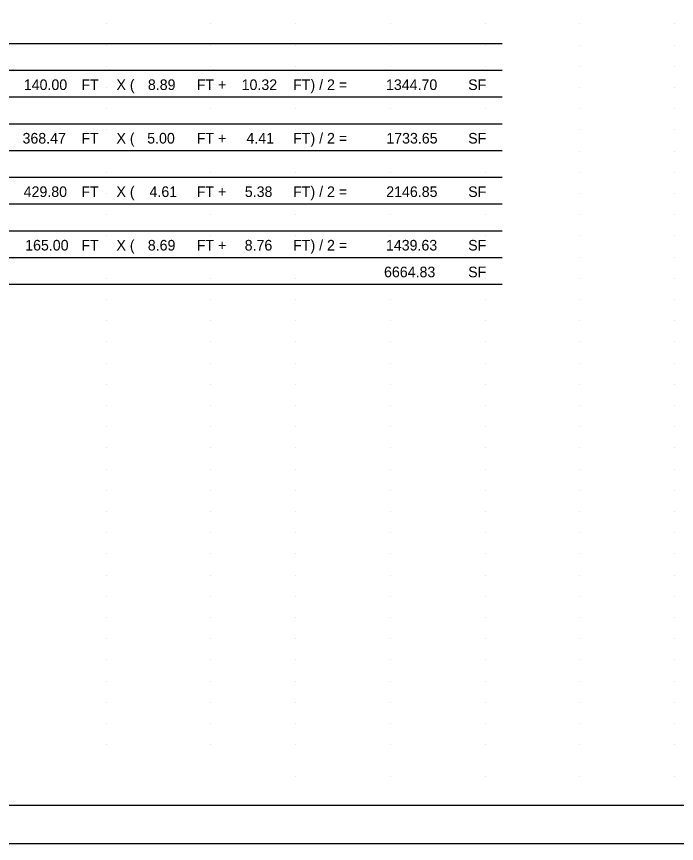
# Model space of a CAD drawing. Extents: x 2073163.5 to 2073197.5, y 634076.4 to 634098.4.
# Drawn here: x 2073171.63 to 2073180.34, y 634076.43 to 634087.36 of the extents above; entities that cross this region are included whole.
import ezdxf

# ---------------------------------------------------------------- set-up
doc = ezdxf.new("R2010")
doc.units = 0
for name, color, linetype in [('SC_Scratch1', 7, 'Continuous'), ('SH_Border', 7, 'Continuous'), ('SH_Cut_Line', 7, 'Continuous'), ('SH_Data', 7, 'Continuous'), ('SH_Text', 7, 'Continuous')]:
    doc.layers.add(name, color=color, linetype=linetype)

msp = doc.modelspace()

# ---------------------------------------------------------------- linework, layer by layer
at = {"layer": 'SC_Scratch1'}
for p, q in [((2073165.829, 634087.001), (2073178.043, 634087.001)), ((2073165.829, 634086.648), (2073178.043, 634086.648)), ((2073165.829, 634086.294), (2073178.043, 634086.294)), ((2073165.829, 634085.941), (2073178.043, 634085.941)), ((2073165.829, 634085.588), (2073178.043, 634085.588)), ((2073165.829, 634085.234), (2073178.043, 634085.234)), ((2073165.829, 634084.881), (2073178.043, 634084.881)), ((2073165.829, 634084.528), (2073178.043, 634084.528)), ((2073165.829, 634084.174), (2073178.043, 634084.174)), ((2073165.829, 634083.821), (2073178.043, 634083.821))]:
    msp.add_line(p, q, dxfattribs=at)
at = {"layer": 'SH_Border'}
msp.add_lwpolyline([(2073165.007, 634097.934), (2073197.007, 634097.934), (2073197.007, 634076.934), (2073165.007, 634076.934)], close=True, dxfattribs=at)
at = {"layer": 'SH_Cut_Line'}
msp.add_lwpolyline([(2073163.507, 634076.434), (2073197.507, 634076.434), (2073197.507, 634098.434), (2073163.507, 634098.434)], close=True, dxfattribs=at)
at = {"layer": 'SH_Data'}
for p, q in [((2073172.821, 634087.258), (2073172.821, 634087.258)), ((2073174.196, 634087.258), (2073174.196, 634087.258)), ((2073175.321, 634087.258), (2073175.321, 634087.258)), ((2073176.571, 634087.258), (2073176.571, 634087.258)), ((2073177.821, 634087.258), (2073177.821, 634087.258)), ((2073179.071, 634087.258), (2073179.071, 634087.258)), ((2073180.321, 634087.258), (2073180.321, 634087.258)), ((2073172.821, 634086.978), (2073172.821, 634086.978)), ((2073174.196, 634086.978), (2073174.196, 634086.978)), ((2073175.321, 634086.978), (2073175.321, 634086.978)), ((2073176.571, 634086.978), (2073176.571, 634086.978)), ((2073177.821, 634086.978), (2073177.821, 634086.978)), ((2073179.071, 634086.978), (2073179.071, 634086.978)), ((2073180.321, 634086.978), (2073180.321, 634086.978)), ((2073172.821, 634086.698), (2073172.821, 634086.698)), ((2073174.196, 634086.698), (2073174.196, 634086.698)), ((2073175.321, 634086.698), (2073175.321, 634086.698)), ((2073176.571, 634086.698), (2073176.571, 634086.698)), ((2073177.821, 634086.698), (2073177.821, 634086.698)), ((2073179.071, 634086.698), (2073179.071, 634086.698)), ((2073180.321, 634086.698), (2073180.321, 634086.698)), ((2073172.821, 634086.418), (2073172.821, 634086.418)), ((2073174.196, 634086.418), (2073174.196, 634086.418)), ((2073175.321, 634086.418), (2073175.321, 634086.418)), ((2073176.571, 634086.418), (2073176.571, 634086.418)), ((2073177.821, 634086.418), (2073177.821, 634086.418)), ((2073179.071, 634086.418), (2073179.071, 634086.418)), ((2073180.321, 634086.418), (2073180.321, 634086.418)), ((2073172.821, 634086.138), (2073172.821, 634086.138)), ((2073174.196, 634086.138), (2073174.196, 634086.138)), ((2073175.321, 634086.138), (2073175.321, 634086.138)), ((2073176.571, 634086.138), (2073176.571, 634086.138)), ((2073177.821, 634086.138), (2073177.821, 634086.138)), ((2073179.071, 634086.138), (2073179.071, 634086.138)), ((2073180.321, 634086.138), (2073180.321, 634086.138)), ((2073172.821, 634085.858), (2073172.821, 634085.858)), ((2073174.196, 634085.858), (2073174.196, 634085.858)), ((2073175.321, 634085.858), (2073175.321, 634085.858)), ((2073176.571, 634085.858), (2073176.571, 634085.858)), ((2073177.821, 634085.858), (2073177.821, 634085.858)), ((2073179.071, 634085.858), (2073179.071, 634085.858)), ((2073180.321, 634085.858), (2073180.321, 634085.858)), ((2073172.821, 634085.578), (2073172.821, 634085.578)), ((2073174.196, 634085.578), (2073174.196, 634085.578)), ((2073175.321, 634085.578), (2073175.321, 634085.578)), ((2073176.571, 634085.578), (2073176.571, 634085.578)), ((2073177.821, 634085.578), (2073177.821, 634085.578)), ((2073179.071, 634085.578), (2073179.071, 634085.578)), ((2073180.321, 634085.578), (2073180.321, 634085.578)), ((2073172.821, 634085.298), (2073172.821, 634085.298)), ((2073174.196, 634085.298), (2073174.196, 634085.298)), ((2073175.321, 634085.298), (2073175.321, 634085.298)), ((2073176.571, 634085.298), (2073176.571, 634085.298)), ((2073177.821, 634085.298), (2073177.821, 634085.298)), ((2073179.071, 634085.298), (2073179.071, 634085.298)), ((2073180.321, 634085.298), (2073180.321, 634085.298)), ((2073172.821, 634085.018), (2073172.821, 634085.018)), ((2073174.196, 634085.018), (2073174.196, 634085.018)), ((2073175.321, 634085.018), (2073175.321, 634085.018)), ((2073176.571, 634085.018), (2073176.571, 634085.018)), ((2073177.821, 634085.018), (2073177.821, 634085.018)), ((2073179.071, 634085.018), (2073179.071, 634085.018)), ((2073180.321, 634085.018), (2073180.321, 634085.018)), ((2073172.821, 634084.738), (2073172.821, 634084.738)), ((2073174.196, 634084.738), (2073174.196, 634084.738)), ((2073175.321, 634084.738), (2073175.321, 634084.738)), ((2073176.571, 634084.738), (2073176.571, 634084.738)), ((2073177.821, 634084.738), (2073177.821, 634084.738)), ((2073179.071, 634084.738), (2073179.071, 634084.738)), ((2073180.321, 634084.738), (2073180.321, 634084.738)), ((2073172.821, 634084.458), (2073172.821, 634084.458)), ((2073174.196, 634084.458), (2073174.196, 634084.458)), ((2073175.321, 634084.458), (2073175.321, 634084.458)), ((2073176.571, 634084.458), (2073176.571, 634084.458)), ((2073177.821, 634084.458), (2073177.821, 634084.458)), ((2073179.071, 634084.458), (2073179.071, 634084.458)), ((2073180.321, 634084.458), (2073180.321, 634084.458)), ((2073172.821, 634084.178), (2073172.821, 634084.178)), ((2073174.196, 634084.178), (2073174.196, 634084.178)), ((2073175.321, 634084.178), (2073175.321, 634084.178)), ((2073176.571, 634084.178), (2073176.571, 634084.178)), ((2073177.821, 634084.178), (2073177.821, 634084.178)), ((2073179.071, 634084.178), (2073179.071, 634084.178)), ((2073180.321, 634084.178), (2073180.321, 634084.178)), ((2073172.821, 634083.898), (2073172.821, 634083.898)), ((2073174.196, 634083.898), (2073174.196, 634083.898)), ((2073175.321, 634083.898), (2073175.321, 634083.898)), ((2073176.571, 634083.898), (2073176.571, 634083.898)), ((2073177.821, 634083.898), (2073177.821, 634083.898)), ((2073179.071, 634083.898), (2073179.071, 634083.898)), ((2073180.321, 634083.898), (2073180.321, 634083.898)), ((2073172.821, 634083.618), (2073172.821, 634083.618)), ((2073174.196, 634083.618), (2073174.196, 634083.618)), ((2073175.321, 634083.618), (2073175.321, 634083.618)), ((2073176.571, 634083.618), (2073176.571, 634083.618)), ((2073177.821, 634083.618), (2073177.821, 634083.618)), ((2073179.071, 634083.618), (2073179.071, 634083.618)), ((2073180.321, 634083.618), (2073180.321, 634083.618)), ((2073172.821, 634083.338), (2073172.821, 634083.338)), ((2073174.196, 634083.338), (2073174.196, 634083.338)), ((2073175.321, 634083.338), (2073175.321, 634083.338)), ((2073176.571, 634083.338), (2073176.571, 634083.338)), ((2073177.821, 634083.338), (2073177.821, 634083.338)), ((2073179.071, 634083.338), (2073179.071, 634083.338)), ((2073180.321, 634083.338), (2073180.321, 634083.338)), ((2073172.821, 634083.058), (2073172.821, 634083.058)), ((2073174.196, 634083.058), (2073174.196, 634083.058)), ((2073175.321, 634083.058), (2073175.321, 634083.058)), ((2073176.571, 634083.058), (2073176.571, 634083.058)), ((2073177.821, 634083.058), (2073177.821, 634083.058)), ((2073179.071, 634083.058), (2073179.071, 634083.058)), ((2073180.321, 634083.058), (2073180.321, 634083.058)), ((2073172.821, 634082.778), (2073172.821, 634082.778)), ((2073174.196, 634082.778), (2073174.196, 634082.778)), ((2073175.321, 634082.778), (2073175.321, 634082.778)), ((2073176.571, 634082.778), (2073176.571, 634082.778)), ((2073177.821, 634082.778), (2073177.821, 634082.778)), ((2073179.071, 634082.778), (2073179.071, 634082.778)), ((2073180.321, 634082.778), (2073180.321, 634082.778)), ((2073172.821, 634082.498), (2073172.821, 634082.498)), ((2073174.196, 634082.498), (2073174.196, 634082.498)), ((2073175.321, 634082.498), (2073175.321, 634082.498)), ((2073176.571, 634082.498), (2073176.571, 634082.498)), ((2073177.821, 634082.498), (2073177.821, 634082.498)), ((2073179.071, 634082.498), (2073179.071, 634082.498)), ((2073180.321, 634082.498), (2073180.321, 634082.498)), ((2073172.821, 634082.218), (2073172.821, 634082.218)), ((2073174.196, 634082.218), (2073174.196, 634082.218)), ((2073175.321, 634082.218), (2073175.321, 634082.218)), ((2073176.571, 634082.218), (2073176.571, 634082.218)), ((2073177.821, 634082.218), (2073177.821, 634082.218)), ((2073179.071, 634082.218), (2073179.071, 634082.218)), ((2073180.321, 634082.218), (2073180.321, 634082.218)), ((2073172.821, 634081.938), (2073172.821, 634081.938)), ((2073174.196, 634081.938), (2073174.196, 634081.938)), ((2073175.321, 634081.938), (2073175.321, 634081.938)), ((2073176.571, 634081.938), (2073176.571, 634081.938)), ((2073177.821, 634081.938), (2073177.821, 634081.938)), ((2073179.071, 634081.938), (2073179.071, 634081.938)), ((2073180.321, 634081.938), (2073180.321, 634081.938)), ((2073172.821, 634081.658), (2073172.821, 634081.658)), ((2073174.196, 634081.658), (2073174.196, 634081.658)), ((2073175.321, 634081.658), (2073175.321, 634081.658)), ((2073176.571, 634081.658), (2073176.571, 634081.658)), ((2073177.821, 634081.658), (2073177.821, 634081.658)), ((2073179.071, 634081.658), (2073179.071, 634081.658)), ((2073180.321, 634081.658), (2073180.321, 634081.658)), ((2073172.821, 634081.378), (2073172.821, 634081.378)), ((2073174.196, 634081.378), (2073174.196, 634081.378)), ((2073175.321, 634081.378), (2073175.321, 634081.378)), ((2073176.571, 634081.378), (2073176.571, 634081.378)), ((2073177.821, 634081.378), (2073177.821, 634081.378)), ((2073179.071, 634081.378), (2073179.071, 634081.378)), ((2073180.321, 634081.378), (2073180.321, 634081.378)), ((2073172.821, 634081.098), (2073172.821, 634081.098)), ((2073174.196, 634081.098), (2073174.196, 634081.098)), ((2073175.321, 634081.098), (2073175.321, 634081.098)), ((2073176.571, 634081.098), (2073176.571, 634081.098)), ((2073177.821, 634081.098), (2073177.821, 634081.098)), ((2073179.071, 634081.098), (2073179.071, 634081.098)), ((2073180.321, 634081.098), (2073180.321, 634081.098)), ((2073172.821, 634080.818), (2073172.821, 634080.818)), ((2073174.196, 634080.818), (2073174.196, 634080.818)), ((2073175.321, 634080.818), (2073175.321, 634080.818)), ((2073176.571, 634080.818), (2073176.571, 634080.818)), ((2073177.821, 634080.818), (2073177.821, 634080.818)), ((2073179.071, 634080.818), (2073179.071, 634080.818)), ((2073180.321, 634080.818), (2073180.321, 634080.818)), ((2073172.821, 634080.538), (2073172.821, 634080.538)), ((2073174.196, 634080.538), (2073174.196, 634080.538)), ((2073175.321, 634080.538), (2073175.321, 634080.538)), ((2073176.571, 634080.538), (2073176.571, 634080.538)), ((2073177.821, 634080.538), (2073177.821, 634080.538)), ((2073179.071, 634080.538), (2073179.071, 634080.538)), ((2073180.321, 634080.538), (2073180.321, 634080.538)), ((2073172.821, 634080.258), (2073172.821, 634080.258)), ((2073174.196, 634080.258), (2073174.196, 634080.258)), ((2073175.321, 634080.258), (2073175.321, 634080.258)), ((2073176.571, 634080.258), (2073176.571, 634080.258)), ((2073177.821, 634080.258), (2073177.821, 634080.258)), ((2073179.071, 634080.258), (2073179.071, 634080.258)), ((2073180.321, 634080.258), (2073180.321, 634080.258)), ((2073172.821, 634079.978), (2073172.821, 634079.978)), ((2073174.196, 634079.978), (2073174.196, 634079.978)), ((2073175.321, 634079.978), (2073175.321, 634079.978)), ((2073176.571, 634079.978), (2073176.571, 634079.978)), ((2073177.821, 634079.978), (2073177.821, 634079.978)), ((2073179.071, 634079.978), (2073179.071, 634079.978)), ((2073180.321, 634079.978), (2073180.321, 634079.978)), ((2073172.821, 634079.698), (2073172.821, 634079.698)), ((2073174.196, 634079.698), (2073174.196, 634079.698)), ((2073175.321, 634079.698), (2073175.321, 634079.698)), ((2073176.571, 634079.698), (2073176.571, 634079.698)), ((2073177.821, 634079.698), (2073177.821, 634079.698)), ((2073179.071, 634079.698), (2073179.071, 634079.698)), ((2073180.321, 634079.698), (2073180.321, 634079.698)), ((2073172.821, 634079.418), (2073172.821, 634079.418)), ((2073174.196, 634079.418), (2073174.196, 634079.418)), ((2073175.321, 634079.418), (2073175.321, 634079.418)), ((2073176.571, 634079.418), (2073176.571, 634079.418)), ((2073177.821, 634079.418), (2073177.821, 634079.418)), ((2073179.071, 634079.418), (2073179.071, 634079.418)), ((2073180.321, 634079.418), (2073180.321, 634079.418)), ((2073172.821, 634079.138), (2073172.821, 634079.138)), ((2073174.196, 634079.138), (2073174.196, 634079.138)), ((2073175.321, 634079.138), (2073175.321, 634079.138)), ((2073176.571, 634079.138), (2073176.571, 634079.138)), ((2073177.821, 634079.138), (2073177.821, 634079.138)), ((2073179.071, 634079.138), (2073179.071, 634079.138)), ((2073180.321, 634079.138), (2073180.321, 634079.138)), ((2073172.821, 634078.858), (2073172.821, 634078.858)), ((2073174.196, 634078.858), (2073174.196, 634078.858)), ((2073175.321, 634078.858), (2073175.321, 634078.858)), ((2073176.571, 634078.858), (2073176.571, 634078.858)), ((2073177.821, 634078.858), (2073177.821, 634078.858)), ((2073179.071, 634078.858), (2073179.071, 634078.858)), ((2073180.321, 634078.858), (2073180.321, 634078.858)), ((2073172.821, 634078.578), (2073172.821, 634078.578)), ((2073174.196, 634078.578), (2073174.196, 634078.578)), ((2073175.321, 634078.578), (2073175.321, 634078.578)), ((2073176.571, 634078.578), (2073176.571, 634078.578)), ((2073177.821, 634078.578), (2073177.821, 634078.578)), ((2073179.071, 634078.578), (2073179.071, 634078.578)), ((2073180.321, 634078.578), (2073180.321, 634078.578)), ((2073172.821, 634078.298), (2073172.821, 634078.298)), ((2073174.196, 634078.298), (2073174.196, 634078.298)), ((2073175.321, 634078.298), (2073175.321, 634078.298)), ((2073176.571, 634078.298), (2073176.571, 634078.298)), ((2073177.821, 634078.298), (2073177.821, 634078.298)), ((2073179.071, 634078.298), (2073179.071, 634078.298)), ((2073180.321, 634078.298), (2073180.321, 634078.298)), ((2073172.821, 634078.018), (2073172.821, 634078.018)), ((2073174.196, 634078.018), (2073174.196, 634078.018)), ((2073175.321, 634078.018), (2073175.321, 634078.018)), ((2073176.571, 634078.018), (2073176.571, 634078.018)), ((2073177.821, 634078.018), (2073177.821, 634078.018)), ((2073179.071, 634078.018), (2073179.071, 634078.018)), ((2073180.321, 634078.018), (2073180.321, 634078.018)), ((2073172.821, 634077.738), (2073172.821, 634077.738)), ((2073174.196, 634077.738), (2073174.196, 634077.738)), ((2073175.321, 634077.738), (2073175.321, 634077.738)), ((2073176.571, 634077.738), (2073176.571, 634077.738)), ((2073177.821, 634077.738), (2073177.821, 634077.738)), ((2073179.071, 634077.738), (2073179.071, 634077.738)), ((2073180.321, 634077.738), (2073180.321, 634077.738)), ((2073175.321, 634077.324), (2073175.321, 634077.324)), ((2073176.571, 634077.324), (2073176.571, 634077.324)), ((2073177.821, 634077.324), (2073177.821, 634077.324)), ((2073179.071, 634077.324), (2073179.071, 634077.324)), ((2073180.321, 634077.324), (2073180.321, 634077.324))]:
    msp.add_line(p, q, dxfattribs=at)

# ---------------------------------------------------------------- texts
at = {"layer": 'SH_Text'}
for s, p in [('140.00', (2073171.728, 634086.386)), ('FT', (2073172.488, 634086.386)), ('X (', (2073172.951, 634086.386)), ('8.89', (2073173.366, 634086.386)), ('FT +', (2073174.012, 634086.386)), ('10.32', (2073174.604, 634086.386)), ('FT) / 2 =', (2073175.284, 634086.386)), ('1344.70', (2073176.51, 634086.386)), ('SF ', (2073177.595, 634086.386)), ('368.47', (2073171.711, 634085.679)), ('FT', (2073172.488, 634085.679)), ('X (', (2073172.951, 634085.679)), ('5.00', (2073173.357, 634085.679)), ('FT +', (2073174.012, 634085.679)), ('4.41', (2073174.667, 634085.679)), ('FT) / 2 =', (2073175.284, 634085.679)), ('1733.65', (2073176.514, 634085.679)), ('SF ', (2073177.595, 634085.679)), ('429.80', (2073171.726, 634084.973)), ('FT', (2073172.488, 634084.973)), ('X (', (2073172.951, 634084.973)), ('4.61', (2073173.388, 634084.973)), ('FT +', (2073174.012, 634084.973)), ('5.38', (2073174.646, 634084.973)), ('FT) / 2 =', (2073175.284, 634084.973)), ('2146.85', (2073176.513, 634084.973)), ('SF ', (2073177.595, 634084.973)), ('165.00', (2073171.746, 634084.266)), ('FT', (2073172.488, 634084.266)), ('X (', (2073172.951, 634084.266)), ('8.69', (2073173.365, 634084.266)), ('FT +', (2073174.012, 634084.266)), ('8.76', (2073174.644, 634084.266)), ('FT) / 2 =', (2073175.284, 634084.266)), ('1439.63', (2073176.509, 634084.266)), ('SF ', (2073177.595, 634084.266)), ('6664.83', (2073176.484, 634083.913)), ('SF ', (2073177.595, 634083.913))]:
    msp.add_text(s, height=0.14, rotation=0.0001, dxfattribs=at).set_placement(p)

doc.saveas('drawing.dxf')
